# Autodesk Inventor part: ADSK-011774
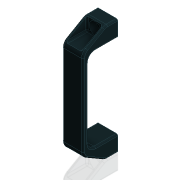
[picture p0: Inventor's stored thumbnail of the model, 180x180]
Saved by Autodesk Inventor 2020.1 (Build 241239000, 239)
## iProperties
Created: 2000-03
Part Number: ADSK-011774
Material: Pearson HRS
Description: HANDLE,DOOR,5.20 CENTER TO CENTER,BLACK,PLASTIC
Document SubType Name: Modeling
Designer: cmcgourin
Density: 7.83 g/cm^3
Appearance: Servo Black
Mass: 348.597 g
Surface Area: 175.952 cm^2
Volume: 44.5207 cm^3
Control State: 0
Master: False
Checked Out: False
Shininess: 0.0
Length Units: 11269
Angle Units: 11279
Time Units: 11290
Mass Units: 11283
Length Display Precision: 3
Angle Display Precision: 2
Compacted: True
Cutlength: 23.25
Material Desc: Material Description goes here
Material_Number: Pearson
Dimensions: 27x150x45 mm
Mass: 0,349 kg
DocNumber: ADSK-011774.ipt
Folder: 01 - Themengebiete\Simplification\01 - Packaging machine\
VDS_Category: 3D Komponenten
Density: 0.0
Volumn: 0.0
Area: 0.0
PropertySet Name: Model Information
Author: cmcgourin
Revision Number: -
Title: handle
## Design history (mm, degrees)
node "Extrusion1" dims "d11" = 27, "d12" = 0
  sketch "Sketch3"
    geometry: L1 (-75, -45)-(-75, -29); L2 (-75, -29)-(-58.257, 0); L3 (-58.257, 0)-(58.257, 0); L4 (58.257, 0)-(75, -29); L5 (75, -29)-(75, -45); L6 (75, -45)-(54, -45); L7 (54, -16)-(54, -45); L8 (45, -7)-(-45, -7); L9 (-54, -16)-(-54, -45); L10 (-75, -45)-(-54, -45); A1 r 9 centre (-45, -16) between (-45, -7) and (-54, -16); A2 r 9 centre (45, -16) between (54, -16) and (45, -7); 4 further points
    constraints: 20 end point, 4 perpendicular, 4 point on circle, 4 point on line, 4 tangent, 2 centre point, 2 horizontal, 2 parallel, 2 vertical, 1 coincident, 1 midpoint
    dimensions: "d0" = 16 distance of L1.start L1.end; "d1" = 108 distance of point (54, -7) point (-54, -7); "d2" = 150 distance of L5.end L1.start; "d3" = 21 distance of L5.end L6.end; "d4" = 60 deg angle of L3 L2 (= d5); "d5" = 60 deg angle of L4 L3; "d7" = 7 distance between parallel lines of L8 L3; "d10" = 116.51369 distance of L2.end L3.end (derived); "d29" = 21 distance of L1.start L9.end (= d3); "d30" = 45 distance between parallel lines of L10 L3; "d31" = 9 radius of A1
node "Extrusion2" dims "d15" = 29, "d16" = 0
  sketch "Sketch5"
    geometry: L1 (0, 116.514)-(-27, 116.514) reference; L2 (0, 133.257)-(-27, 133.257) reference; L3 (-23.75, 116.514)-(-3.25, 116.514); L4 (-3.25, 116.514)-(-3.25, 133.257); L5 (-3.25, 133.257)-(-23.75, 133.257); L6 (-23.75, 133.257)-(-23.75, 116.514); L7 (-27, 133.257)-(-27, 116.514) reference; L8 (0, 133.257)-(0, 116.514) reference; 1 further point
    constraints: 8 end point, 2 midpoint, 2 parallel, 2 point on line, 1 horizontal, 1 perpendicular
    dimensions: "d32" = 20.5 distance between parallel lines of L6 L4
mirror "Spiegeln1"
fillet "Rundung1" dims "d34" = 10
fillet "Rundung2" dims "d35" = 2
fillet "Rundung3" dims "d36" = 2
node "Hole1" dims "d23" = 9, "d24" = 15, "d25" = 9, "d26" = 60 deg, "d27" = 19.05, "d28" = 118 deg, "d33" = 6
  sketch "Sketch7"
    geometry: L1 (-13.5, 124.257)-(-13.5, -7.743); 2 further points
    constraints: 2 end point, 1 coincident, 1 midpoint, 1 vertical
    dimensions: "d21" = 132 distance of L1.start L1.end
node "Solide1"
node "Corps solides"
node "Corps surfaciques"
